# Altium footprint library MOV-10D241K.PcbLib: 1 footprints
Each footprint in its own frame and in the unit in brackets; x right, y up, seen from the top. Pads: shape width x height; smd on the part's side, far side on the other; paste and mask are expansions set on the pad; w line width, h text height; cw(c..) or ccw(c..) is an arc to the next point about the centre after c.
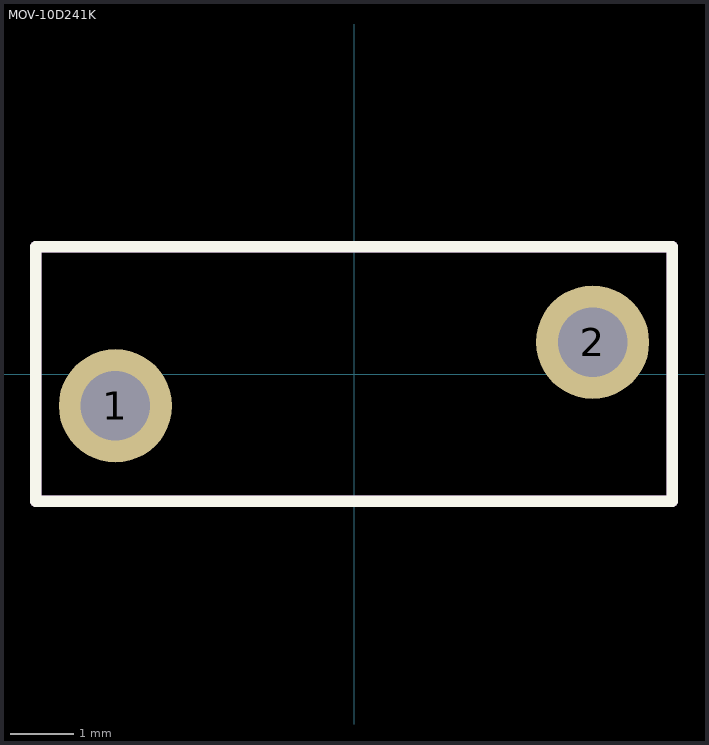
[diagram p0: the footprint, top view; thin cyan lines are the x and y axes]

## MOV-10D241K [mil] "Bourns MOV P/N MOV-10D241K"
height 590.55
pads (2):
  round 70 hole 43: 1(-147.64,-19.68) 2(147.64,19.68)
Top Overlay:
  lines w7: -196.85,-78.74 196.85,-78.74 196.85,78.74 -196.85,78.74 -196.85,-78.74
M5 Assembly Top:
  lines w7: -196.85,-78.74 -196.85,78.74 196.85,78.74 196.85,-78.74 -196.85,-78.74
  text ".Designator" at -161.42,-19.68 h72.83
3D body "mov-10d241k.stp": height 620.08, standoff -777.56, extent -246.06,-78.73 246.07,78.75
